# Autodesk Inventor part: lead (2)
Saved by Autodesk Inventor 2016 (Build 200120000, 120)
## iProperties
Created: 2016-09
Part Number: lead (2)
Material: Generic
Document SubType Name: Modeling
Designer: Administrator
Appearance: Generic
Author: Administrator
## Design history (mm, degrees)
feature "Body2"
feature "Body3"
feature "Body17"
body "Solid1"
body "Solid2"
body "Solid3"
